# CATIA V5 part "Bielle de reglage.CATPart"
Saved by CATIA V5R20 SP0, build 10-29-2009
Part number: Bielle de reglage
Publications: "Face"
Bounding box of the stored display mesh (mm): x -10 to 10, y 175.336 to 250.398, z 154.367 to 179.367
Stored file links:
  C:\Users\thinkmotion1\Desktop\Khaled_IAO_Pack2\IAO_2010_1412_jclement\Non_Optimise\Bielle de reglage.CATPart
  C:\Users\thinkmotion1\Desktop\Khaled_IAO_Pack2\IAO_2010_1412_jclement\Non_Optimise\Synthese IAO_2.CATProduct
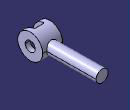
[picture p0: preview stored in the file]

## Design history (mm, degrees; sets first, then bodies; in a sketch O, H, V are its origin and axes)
Set1
  DatumSurface1: linked copy from another document
  DatumCurve1: linked copy from another document
  DatumCurve2: linked copy from another document
Set2
  Point1: type OnSurface, Support face of Pad1 from Sketch1.A1, Length 19.5, Direction zx-plane
  Plane1: type Tangent, Support face of Pad1 from Sketch1.A1, RefPoint Point1
Body1 (main body)
  Sketch1 on face of DatumSurface1, origin (-5, 0, 0), H (0, 1, 0), V (0, 0, 1)
    circle A1 centre (187.8357, 166.8666) radius 12.5
    circle A2 centre (187.8357, 166.8666) radius 5
    reference projected circle E1 centre (187.8357, 166.8666) radius 5 from edge of DatumCurve1
    radius A1 = 12.5
    coincidence: A2 E1
  Pad1: profile Sketch1, direction (-1, 0, 0), length 5, opposite side length 15
  Sketch2 on xy-plane, origin (0, 0, 0), H (1, 0, 0), V (0, 1, 0)
    line L1 (-5, 173.3962) -> (5, 173.3962)
    line L2 (5, 173.3962) -> (5, 186.9915)
    line L3 (5, 186.9915) -> (-5, 186.9915)
    line L4 (-5, 186.9915) -> (-5, 173.3962)
    reference intersected line E1 through (0, 0) direction (0, 1) from yz-plane
    distance L2 L4 = 10
    horizontal: L1 H, L3 H
    vertical: L2 V, L4 V
    symmetry: L4 L2 E1
  Pocket1: profile Sketch2, direction (0, 0, 1), through (limit type 6)
  Sketch3 on Plane1, origin (0, 202.1494, -1.0525), H (1, 0, 0), V (0, -0.0108, 0.9999)
    circle A1 centre (0, 167.926) radius 6
    point P1 (0, 167.926)
    radius A1 = 6
    coincidence: P1 V
  Pad2: profile Sketch3, direction (0, 0.9999, 0.0108), length 50, opposite side length 2
  Thread1: diameter 12, depth 49, pitch 1, on face of Pad2 from Sketch3.A1, from end face of Pad2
